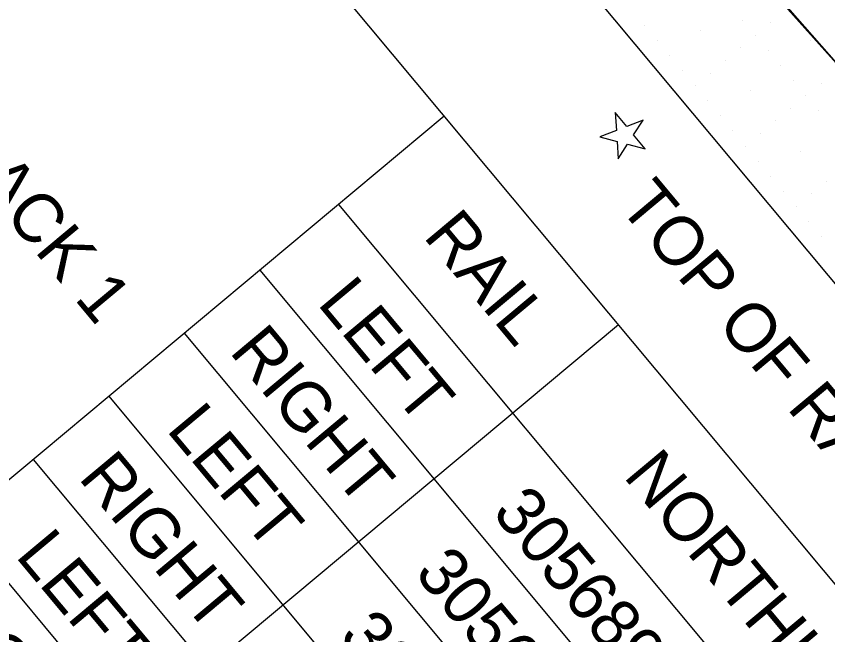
# Model space of a CAD drawing. Extents: x 2042995 to 2043795, y 305365 to 306249.
# Drawn here: x 2043107.34 to 2043148.6, y 305955.46 to 305986.89 of the extents above; entities that cross this region are included whole.
import ezdxf

# ---------------------------------------------------------------- set-up
doc = ezdxf.new("R2010")
doc.units = 0
for name, color, linetype in [('BR_BORDER LINES', 7, 'Continuous'), ('BR_CONCRETE', 7, 'Continuous'), ('BR_EXIST_GROUND_LT', 7, 'Continuous'), ('BR_EXIST_GROUND_RT', 7, 'Continuous'), ('BR_GRID DOTS', 7, 'Continuous'), ('BR_TABLE LINES', 7, 'Continuous'), ('BR_TEXT', 7, 'Continuous')]:
    doc.layers.add(name, color=color, linetype=linetype)

msp = doc.modelspace()

# ---------------------------------------------------------------- linework, layer by layer
at = {"layer": 'BR_BORDER LINES'}
msp.add_line((2043123.144, 306004.214), (2043200.067, 305912.112), dxfattribs=at)
at = {"layer": 'BR_CONCRETE'}
msp.add_spline([(2043139.109, 306017.548), (2043148.199, 306007.16), (2043160.233, 305993.368), (2043172.245, 305979.557), (2043184.234, 305965.727), (2043196.201, 305951.879), (2043208.145, 305938.012), (2043220.067, 305924.126), (2043231.966, 305910.221), (2043243.843, 305896.297), (2043255.698, 305882.355), (2043267.529, 305868.394), (2043279.339, 305854.414), (2043291.126, 305840.415), (2043302.89, 305826.398), (2043314.632, 305812.361), (2043326.352, 305798.306), (2043338.049, 305784.233), (2043349.724, 305770.14), (2043361.376, 305756.029), (2043373.005, 305741.899), (2043384.613, 305727.75), (2043396.197, 305713.582), (2043407.76, 305699.396), (2043419.299, 305685.191), (2043430.817, 305670.967), (2043442.311, 305656.724), (2043453.784, 305642.463), (2043465.234, 305628.182), (2043476.661, 305613.883), (2043488.066, 305599.566), (2043499.448, 305585.229), (2043510.808, 305570.874), (2043522.146, 305556.5), (2043533.461, 305542.107), (2043544.753, 305527.695), (2043547.219, 305524.543)], degree=3, dxfattribs=at)
at = {"layer": 'BR_EXIST_GROUND_LT'}
msp.add_lwpolyline([(2043127.956, 306008.234), (2043136.17, 305998.877), (2043139.136, 305995.79), (2043151.989, 305981.161), (2043154.962, 305977.692), (2043168.609, 305962.472), (2043171.467, 305959.143), (2043185.235, 305943.789), (2043187.984, 305940.592), (2043201.866, 305925.112), (2043204.513, 305922.037), (2043218.502, 305906.439), (2043218.632, 305906.288), (2043219.569, 305905.47), (2043220.034, 305904.951), (2043224.372, 305899.652), (2043230.892, 305893.533)], dxfattribs=at)
at = {"layer": 'BR_EXIST_GROUND_RT'}
msp.add_lwpolyline([(2043127.871, 306008.162), (2043135.626, 305999.492), (2043140.757, 305993.755), (2043152.231, 305980.926), (2043152.788, 305980.304), (2043164.384, 305967.114), (2043169.234, 305961.496), (2043181.072, 305948.031), (2043185.685, 305942.691), (2043197.744, 305928.975)], dxfattribs=at)
at = {"layer": 'BR_GRID DOTS'}
for p, q in [((2043139.296, 305986.435), (2043139.296, 305986.435)), ((2043144.289, 305986.696), (2043144.289, 305986.696)), ((2043145.697, 305986.57), (2043145.697, 305986.57)), ((2043142.113, 305986.182), (2043142.113, 305986.182)), ((2043138.528, 305985.793), (2043138.528, 305985.793)), ((2043139.937, 305985.667), (2043139.937, 305985.667)), ((2043144.93, 305985.929), (2043144.93, 305985.929)), ((2043147.747, 305985.676), (2043147.747, 305985.676)), ((2043144.162, 305985.288), (2043144.162, 305985.288)), ((2043140.578, 305984.899), (2043140.578, 305984.899)), ((2043145.571, 305985.161), (2043145.571, 305985.161)), ((2043143.395, 305984.646), (2043143.395, 305984.646)), ((2043146.212, 305984.393), (2043146.212, 305984.393)), ((2043141.219, 305984.132), (2043141.219, 305984.132)), ((2043142.627, 305984.005), (2043142.627, 305984.005)), ((2043146.853, 305983.626), (2043146.853, 305983.626)), ((2043141.86, 305983.364), (2043141.86, 305983.364)), ((2043148.262, 305983.499), (2043148.262, 305983.499)), ((2043141.092, 305982.723), (2043141.092, 305982.723)), ((2043144.677, 305983.111), (2043144.677, 305983.111)), ((2043147.494, 305982.858), (2043147.494, 305982.858)), ((2043142.501, 305982.597), (2043142.501, 305982.597)), ((2043146.727, 305982.217), (2043146.727, 305982.217)), ((2043148.135, 305982.091), (2043148.135, 305982.091)), ((2043143.142, 305981.829), (2043143.142, 305981.829)), ((2043145.959, 305981.576), (2043145.959, 305981.576)), ((2043143.783, 305981.062), (2043143.783, 305981.062)), ((2043145.192, 305980.935), (2043145.192, 305980.935)), ((2043144.424, 305980.294), (2043144.424, 305980.294)), ((2043147.241, 305980.041), (2043147.241, 305980.041)), ((2043143.656, 305979.653), (2043143.656, 305979.653)), ((2043145.065, 305979.527), (2043145.065, 305979.527)), ((2043145.706, 305978.759), (2043145.706, 305978.759)), ((2043148.523, 305978.506), (2043148.523, 305978.506)), ((2043146.347, 305977.992), (2043146.347, 305977.992)), ((2043147.756, 305977.865), (2043147.756, 305977.865)), ((2043146.988, 305977.224), (2043146.988, 305977.224)), ((2043146.221, 305976.583), (2043146.221, 305976.583)), ((2043147.629, 305976.457), (2043147.629, 305976.457)), ((2043148.27, 305975.689), (2043148.27, 305975.689))]:
    msp.add_line(p, q, dxfattribs=at)
at = {"layer": 'BR_TABLE LINES'}
for p, q in [((2043115.631, 305997.939), (2043192.554, 305905.837)), ((2043129.093, 305981.822), (2043054.481, 305919.506)), ((2043123.72, 305977.334), (2043187.182, 305901.35)), ((2043119.72, 305973.993), (2043183.181, 305898.009)), ((2043137.956, 305971.209), (2043063.344, 305908.893)), ((2043115.882, 305970.788), (2043179.344, 305894.804)), ((2043112.045, 305967.583), (2043175.506, 305891.599)), ((2043108.207, 305964.378), (2043171.669, 305888.394)), ((2043104.369, 305961.173), (2043167.831, 305885.189))]:
    msp.add_line(p, q, dxfattribs=at)
at = {"layer": 'BR_TEXT'}
msp.add_lwpolyline([(2043137.866, 305981.088), (2043137.018, 305980.758), (2043137.898, 305980.532), (2043137.939, 305979.65), (2043138.42, 305980.394), (2043139.318, 305980.163), (2043138.729, 305980.868), (2043139.211, 305981.612), (2043138.386, 305981.294), (2043137.797, 305981.999)], close=True, dxfattribs=at)

# ---------------------------------------------------------------- texts
for s, p in [('TRACK 1', (2043102.398, 305981.948)), ('TOP OF RAIL SURVEY ELEVATIONS', (2043137.912, 305977.242)), ('RAIL', (2043127.989, 305975.695)), ('LEFT', (2043122.604, 305972.283)), ('RIGHT', (2043118.131, 305969.84)), ('LEFT', (2043114.929, 305965.873)), ('RIGHT', (2043110.456, 305963.429)), ('NORTHING', (2043138.166, 305963.509)), ('305689.8071', (2043131.481, 305961.655)), ('LEFT', (2043107.254, 305959.463)), ('305686.9792', (2043127.537, 305958.577)), ('RIGHT', (2043102.78, 305957.019)), ('305900.8093', (2043123.7, 305955.372))]:
    msp.add_text(s, height=2.5, rotation=309.8684, dxfattribs=at).set_placement(p)

doc.saveas('drawing.dxf')
